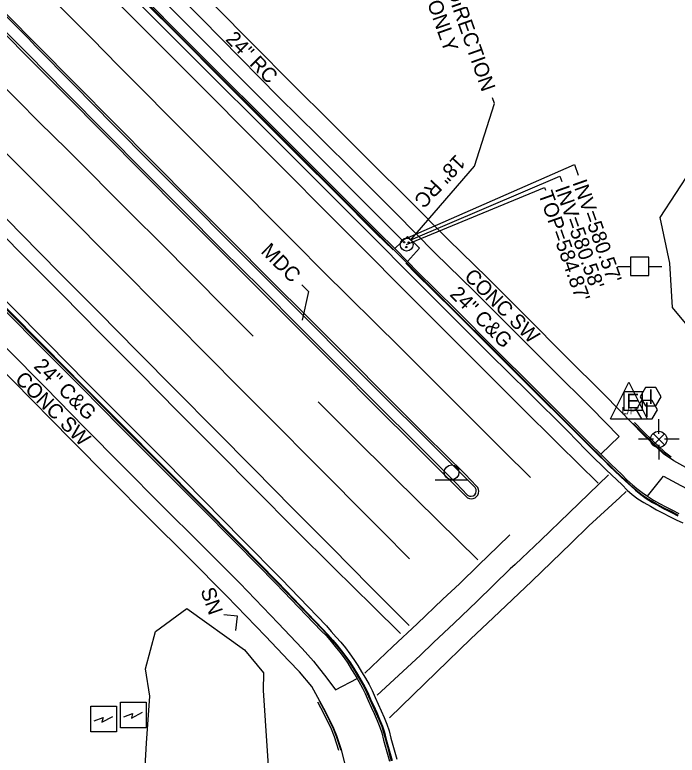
# Model space of a CAD drawing. Extents: x 2004847 to 2009016, y 1134161 to 1140101.
# Drawn here: x 2008295.3 to 2008475.6, y 1139772.3 to 1139973.7 of the extents above; entities that cross this region are included whole.
import ezdxf

# ---------------------------------------------------------------- set-up
doc = ezdxf.new("R2010")
doc.units = 0
for name, color, linetype in [('RD_EX_BldgApp', 7, 'Continuous'), ('RD_EX_Conc', 7, 'Continuous'), ('RD_EX_Curb', 7, 'Continuous'), ('RD_EX_DR_Inlet', 7, 'Continuous'), ('RD_EX_DR_Inlet_txCode', 7, 'Continuous'), ('RD_EX_DR_Pipe', 7, 'Continuous'), ('RD_EX_DR_Pipe_txCode', 7, 'Continuous'), ('RD_EX_Misc', 7, 'Continuous'), ('RD_EX_Road', 7, 'Continuous'), ('RD_EX_SU_Elec', 7, 'Continuous'), ('RD_EX_SU_Pole', 7, 'Continuous'), ('RD_EX_SU_TX_Nonpot', 7, 'Continuous'), ('RD_EX_UT', 7, 'Continuous'), ('RD_EX_VEG', 7, 'Continuous'), ('RD_Sketch3', 7, 'Continuous')]:
    doc.layers.add(name, color=color, linetype=linetype)

msp = doc.modelspace()

# ---------------------------------------------------------------- linework, layer by layer
at = {"layer": 'RD_EX_BldgApp'}
msp.add_line((2008409.72, 1139847.24), (2008418.72, 1139847.24), dxfattribs=at)
msp.add_lwpolyline([(2008355.52, 1139806.21), (2008355.97, 1139810.12), (2008352.23, 1139810.46)], dxfattribs=at)
msp.add_circle((2008414.24, 1139849.27), 2, dxfattribs=at)
at = {"layer": 'RD_EX_Conc'}
for points in [[(2008455.81, 1139870.39), (2008445.15, 1139880.94), (2008434.58, 1139891.57), (2008423.99, 1139902.16), (2008413.27, 1139912.62), (2008402.72, 1139923.27), (2008392.08, 1139933.83), (2008381.47, 1139944.43), (2008370.79, 1139954.95), (2008360.26, 1139965.62), (2008349.71, 1139976.27), (2008339.15, 1139986.9), (2008328.55, 1139997.38), (2008318.08, 1140008.11), (2008307.51, 1140018.72), (2008300.23, 1140026.14)], [(2008454.8, 1139854.23), (2008459.88, 1139859.04), (2008452.21, 1139866.78), (2008441.56, 1139877.34), (2008430.98, 1139887.97), (2008420.38, 1139898.56), (2008409.66, 1139909.02), (2008399.16, 1139919.72), (2008388.54, 1139930.3), (2008377.9, 1139940.86), (2008367.21, 1139951.38), (2008356.69, 1139962.06), (2008346.14, 1139972.71), (2008335.57, 1139983.34), (2008324.96, 1139993.84), (2008314.49, 1140004.57), (2008303.91, 1140015.18), (2008296.3, 1140022.95)], [(2008219.32, 1139957.21), (2008229.54, 1139946.87), (2008240.33, 1139936.21), (2008250.86, 1139925.54), (2008261.4, 1139914.88), (2008272.13, 1139904.31), (2008282.48, 1139893.45), (2008293.16, 1139882.93), (2008303.69, 1139872.3), (2008314.18, 1139861.59), (2008324.74, 1139850.94), (2008335.32, 1139840.28), (2008346.01, 1139829.71), (2008356.58, 1139819.08), (2008367.03, 1139808.19), (2008373.6, 1139801.37)], [(2008215.56, 1139953.88), (2008225.95, 1139943.38), (2008236.76, 1139932.69), (2008247.29, 1139922.02), (2008257.84, 1139911.37), (2008268.61, 1139900.82), (2008278.97, 1139889.96), (2008289.64, 1139879.44), (2008300.17, 1139868.81), (2008310.66, 1139858.1), (2008321.21, 1139847.45), (2008331.8, 1139836.79), (2008342.5, 1139826.21), (2008353.07, 1139815.57), (2008363.54, 1139804.68), (2008369.92, 1139797.95)], [(2008527.85, 1139868.64), (2008519.87, 1139860.43), (2008516.05, 1139856.68), (2008512.22, 1139852.93), (2008509.74, 1139851.08), (2008507.16, 1139849.33), (2008505.4, 1139848.51), (2008502.42, 1139847.24), (2008499.59, 1139846.5), (2008497.28, 1139846.2), (2008495.25, 1139846.12), (2008493.73, 1139846.1), (2008490.49, 1139846.26), (2008488.14, 1139846.52), (2008485.43, 1139847.17), (2008482.57, 1139848.22), (2008478.8, 1139850.09), (2008474.68, 1139852.36), (2008471.89, 1139854.32), (2008468.58, 1139857.43), (2008465.97, 1139859.95), (2008463.56, 1139862.43), (2008455.81, 1139870.39)], [(2008467.52, 1139842.75), (2008471.87, 1139848.22), (2008476.63, 1139845.66), (2008480.47, 1139843.69), (2008484.23, 1139842.24), (2008487.35, 1139841.68), (2008490.16, 1139841.35), (2008494.2, 1139841.35), (2008494.33, 1139834.12)], [(2008373.6, 1139801.37), (2008376.68, 1139797.89), (2008380.31, 1139793.28), (2008382.62, 1139790.09), (2008388.5, 1139793.17)], [(2008386.07, 1139766.5), (2008385.16, 1139770.21), (2008384.3, 1139773.78), (2008383, 1139777.53), (2008382.13, 1139779.6), (2008380.03, 1139783.98), (2008378.39, 1139786.99), (2008376.16, 1139791), (2008372.86, 1139794.95), (2008369.92, 1139797.95)]]:
    msp.add_lwpolyline(points, dxfattribs=at)
at = {"layer": 'RD_EX_Curb'}
for points in [[(2008452.16, 1139856.81), (2008447.21, 1139861.77), (2008436.58, 1139872.35), (2008425.93, 1139882.92), (2008415.36, 1139893.54), (2008404.67, 1139904.05), (2008402.5, 1139906.32), (2008402.2, 1139906.64), (2008398.74, 1139910.17), (2008394.13, 1139914.7), (2008383.54, 1139925.32), (2008372.91, 1139935.89), (2008362.31, 1139946.49), (2008351.67, 1139957.05), (2008341.09, 1139967.67), (2008330.53, 1139978.32), (2008320.12, 1139989.06), (2008312.75, 1139996.7), (2008311.85, 1139997.58), (2008305.89, 1140003.52), (2008305.41, 1140004.01), (2008294.92, 1140014.72), (2008290.94, 1140018.69)], [(2008401.91, 1139906.34), (2008398.45, 1139909.88), (2008393.84, 1139914.42), (2008383.24, 1139925.01), (2008372.63, 1139935.61), (2008362.03, 1139946.22), (2008351.41, 1139956.8), (2008340.84, 1139967.42), (2008330.28, 1139978.07), (2008319.78, 1139988.73), (2008312.37, 1139996.32), (2008311.55, 1139997.24), (2008305.63, 1140003.25), (2008305.11, 1140003.72), (2008294.6, 1140014.4), (2008290.68, 1140018.42)], [(2008267.85, 1139998.54), (2008278.41, 1139987.96), (2008280.16, 1139986.26), (2008283.69, 1139982.81), (2008288.53, 1139977.97), (2008290.45, 1139975.85), (2008299.08, 1139967.33), (2008301, 1139965.19), (2008311.48, 1139954.64), (2008322.11, 1139943.85), (2008332.65, 1139933.19), (2008343.21, 1139922.57), (2008353.8, 1139911.95), (2008364.4, 1139901.36), (2008375.07, 1139890.68), (2008385.65, 1139880.05), (2008396.18, 1139869.51), (2008406.84, 1139858.89), (2008417.47, 1139848.32), (2008420.62, 1139845.11)], [(2008398.34, 1139909.77), (2008393.69, 1139914.27), (2008383.12, 1139924.9), (2008372.48, 1139935.47), (2008361.88, 1139946.07), (2008351.27, 1139956.66), (2008340.69, 1139967.27), (2008330.13, 1139977.91), (2008319.6, 1139988.55), (2008312.22, 1139996.18), (2008311.55, 1139996.85)], [(2008287.82, 1139974.22), (2008288.25, 1139973.67), (2008298.89, 1139963.1), (2008309.35, 1139952.56), (2008320.03, 1139941.76), (2008330.59, 1139931.13), (2008341.15, 1139920.51), (2008351.73, 1139909.89), (2008362.36, 1139899.33), (2008373.04, 1139888.63), (2008383.65, 1139878.04), (2008394.17, 1139867.51), (2008404.84, 1139856.88), (2008415.44, 1139846.27), (2008418.59, 1139843.07)], [(2008225.08, 1139962.17), (2008234.98, 1139952.15), (2008243.99, 1139943.03), (2008250.27, 1139936.69), (2008250.53, 1139936.45), (2008261.1, 1139925.81), (2008271.68, 1139915.13), (2008282.25, 1139904.49), (2008292.82, 1139893.87), (2008303.36, 1139883.23), (2008313.92, 1139872.59), (2008324.49, 1139861.95), (2008335.05, 1139851.29), (2008345.65, 1139840.65), (2008356.2, 1139830), (2008366.76, 1139819.26)], [(2008225.24, 1139962.31), (2008235.14, 1139952.29), (2008244.13, 1139943.18), (2008250.39, 1139936.8), (2008250.68, 1139936.59), (2008261.25, 1139925.96), (2008271.83, 1139915.27), (2008282.4, 1139904.64), (2008292.97, 1139894.01), (2008303.51, 1139883.38), (2008314.06, 1139872.73), (2008324.63, 1139862.1), (2008335.2, 1139851.44), (2008345.77, 1139840.77), (2008356.34, 1139830.13), (2008366.89, 1139819.39)], [(2008224.78, 1139961.88), (2008234.67, 1139951.84), (2008243.65, 1139942.71), (2008249.96, 1139936.38), (2008250.21, 1139936.13), (2008260.84, 1139925.56), (2008271.34, 1139914.8), (2008281.92, 1139904.17), (2008292.47, 1139893.51), (2008303, 1139882.88), (2008313.55, 1139872.22), (2008324.11, 1139861.58), (2008334.72, 1139850.97), (2008345.34, 1139840.34), (2008355.9, 1139829.69), (2008366.46, 1139818.96)], [(2008451.74, 1139856.36), (2008446.77, 1139861.33), (2008436.14, 1139871.92), (2008425.52, 1139882.5), (2008414.93, 1139893.11), (2008404.24, 1139903.61), (2008402.03, 1139905.87), (2008401.75, 1139906.17)], [(2008451.88, 1139856.49), (2008446.9, 1139861.46), (2008436.27, 1139872.04), (2008425.66, 1139882.64), (2008415.06, 1139893.24), (2008404.42, 1139903.79), (2008402.21, 1139906.04), (2008401.91, 1139906.34)], [(2008463.68, 1139862.53), (2008466.12, 1139860.1), (2008468.72, 1139857.56), (2008471.99, 1139854.49), (2008473.79, 1139853.13)], [(2008464.01, 1139862.81), (2008466.41, 1139860.39), (2008469.01, 1139857.81), (2008472.18, 1139854.84), (2008474.02, 1139853.47)], [(2008451.74, 1139856.36), (2008454.37, 1139853.77), (2008455.8, 1139852.37), (2008457.2, 1139850.94), (2008458.66, 1139849.57), (2008460.11, 1139848.2), (2008461.59, 1139846.85), (2008463.06, 1139845.5), (2008464.25, 1139844.4), (2008465.7, 1139843.19), (2008467.17, 1139842.1), (2008468.88, 1139841.08), (2008470.53, 1139840.2), (2008472.28, 1139839.23), (2008474.04, 1139838.32), (2008475.82, 1139837.41)], [(2008451.88, 1139856.49), (2008454.5, 1139853.89), (2008455.88, 1139852.5), (2008457.29, 1139851.12), (2008458.7, 1139849.73), (2008460.23, 1139848.32), (2008461.7, 1139846.96), (2008463.14, 1139845.58), (2008464.33, 1139844.51), (2008465.8, 1139843.35), (2008467.26, 1139842.28), (2008468.99, 1139841.29), (2008470.6, 1139840.36), (2008472.39, 1139839.46), (2008474.14, 1139838.56), (2008475.93, 1139837.65)], [(2008452.16, 1139856.81), (2008454.8, 1139854.23), (2008456.24, 1139852.84), (2008457.67, 1139851.43), (2008459.09, 1139850.02), (2008460.54, 1139848.65), (2008461.96, 1139847.24), (2008463.44, 1139845.89), (2008464.6, 1139844.89), (2008466.07, 1139843.76), (2008467.52, 1139842.75), (2008469.2, 1139841.7), (2008470.81, 1139840.81), (2008472.57, 1139839.85), (2008474.31, 1139838.94), (2008476.1, 1139838.03)], [(2008366.76, 1139819.26), (2008379.08, 1139806.46), (2008380.42, 1139804.98), (2008381.76, 1139803.5), (2008382.87, 1139802.17), (2008384.15, 1139800.63), (2008385.35, 1139799.03), (2008386.35, 1139797.58), (2008387.45, 1139795.91), (2008388.45, 1139794.28), (2008389.45, 1139792.55), (2008390.4, 1139790.79), (2008391.19, 1139789.27), (2008391.98, 1139787.43), (2008392.82, 1139785.62), (2008393.62, 1139783.82), (2008394.41, 1139781.98), (2008395.23, 1139780.15), (2008395.73, 1139778.49), (2008396.26, 1139776.56), (2008396.74, 1139774.61), (2008397.28, 1139772.72), (2008397.82, 1139770.79)], [(2008366.89, 1139819.39), (2008379.22, 1139806.59), (2008380.57, 1139805.11), (2008381.89, 1139803.61), (2008383.03, 1139802.29), (2008384.28, 1139800.72), (2008385.47, 1139799.12), (2008386.52, 1139797.69), (2008387.59, 1139796), (2008388.62, 1139794.38), (2008389.63, 1139792.65), (2008390.61, 1139790.91), (2008391.41, 1139789.36), (2008392.18, 1139787.52), (2008393.04, 1139785.71), (2008393.85, 1139783.91), (2008394.64, 1139782.07), (2008395.38, 1139780.21), (2008395.92, 1139778.54), (2008396.42, 1139776.6), (2008396.93, 1139774.67), (2008397.47, 1139772.77), (2008398.04, 1139770.85)], [(2008366.46, 1139818.96), (2008378.75, 1139806.16), (2008380.15, 1139804.73), (2008381.48, 1139803.24), (2008382.5, 1139801.89), (2008383.78, 1139800.35), (2008384.97, 1139798.75), (2008385.95, 1139797.34), (2008386.97, 1139795.62), (2008387.99, 1139794.03), (2008388.5, 1139793.17), (2008389.01, 1139792.31), (2008389.99, 1139790.56), (2008390.73, 1139789.07), (2008391.48, 1139787.22), (2008392.34, 1139785.41), (2008393.13, 1139783.62), (2008393.93, 1139781.78), (2008394.69, 1139779.93), (2008395.2, 1139778.34), (2008395.72, 1139776.41), (2008396.25, 1139774.48), (2008396.79, 1139772.58), (2008397.37, 1139770.67)], [(2008378.27, 1139786.93), (2008379.87, 1139783.9), (2008381.96, 1139779.54), (2008382.85, 1139777.48), (2008384.09, 1139773.71)], [(2008383.54, 1139773.55), (2008382.36, 1139777.31), (2008381.52, 1139779.39), (2008379.45, 1139783.68), (2008377.82, 1139786.7)]]:
    msp.add_lwpolyline(points, dxfattribs=at)
msp.add_ellipse((2008419.51, 1139844.19), major_axis=(-1.44, -0.17), ratio=0.999976, start_param=0.761026, end_param=3.708422, dxfattribs=at)
at = {"layer": 'RD_EX_DR_Inlet'}
msp.add_lwpolyline([(2008402.2, 1139906.64), (2008405.51, 1139910.29), (2008402.2, 1139913.4), (2008398.74, 1139910.17)], dxfattribs=at)
for centre, radius in [((2008401.98, 1139911.23), 1.75), ((2008401.31, 1139911.86), 0.175), ((2008402.54, 1139911.79), 0.175), ((2008401.89, 1139910.56), 0.175)]:
    msp.add_circle(centre, radius, dxfattribs=at)
at = {"layer": 'RD_EX_DR_Inlet_txCode'}
for points in [[(2008400.74, 1139912.47), (2008447.7, 1139932.98), (2008448.71, 1139930.12)], [(2008403.12, 1139912.55), (2008443.68, 1139929.85), (2008444.19, 1139928.39)], [(2008401.98, 1139911.23), (2008439.52, 1139926.79), (2008439.8, 1139925.99)]]:
    msp.add_lwpolyline(points, dxfattribs=at)
at = {"layer": 'RD_EX_DR_Pipe'}
for p, q in [((2008309.01, 1140004.51), (2008400.74, 1139912.47)), ((2008403.12, 1139912.55), (2008420.42, 1139932.56))]:
    msp.add_line(p, q, dxfattribs=at)
at = {"layer": 'RD_EX_DR_Pipe_txCode'}
msp.add_lwpolyline([(2008420.42, 1139932.56), (2008425.89, 1139949.57), (2008425.34, 1139951.14)], dxfattribs=at)
at = {"layer": 'RD_EX_Misc'}
for points in [[(2008454.11, 1139846.27), (2008443.41, 1139856.79), (2008432.8, 1139867.39), (2008422.19, 1139877.99), (2008411.58, 1139888.6), (2008400.98, 1139899.21), (2008390.39, 1139909.83), (2008379.79, 1139920.45), (2008369.2, 1139931.07), (2008358.61, 1139941.69), (2008348.02, 1139952.31), (2008337.42, 1139962.93), (2008326.83, 1139973.55), (2008316.24, 1139984.18), (2008305.71, 1139994.86), (2008295.17, 1140005.53), (2008286.38, 1140014.45)], [(2008277.34, 1140006.87), (2008288.12, 1139995.7), (2008295.52, 1139988.25), (2008316.29, 1139967.3), (2008323.54, 1139959.85), (2008343.87, 1139939.49), (2008351.32, 1139932), (2008371.84, 1139911.4), (2008379.17, 1139904.03), (2008400.32, 1139883.13), (2008407.65, 1139875.78), (2008428.3, 1139855.24), (2008435.72, 1139847.81)], [(2008360.19, 1139886.32), (2008352.65, 1139893.87), (2008334.87, 1139911.76), (2008327.42, 1139919.24), (2008309.57, 1139937.06), (2008302.01, 1139944.55), (2008284.22, 1139962.51), (2008276.76, 1139969.99), (2008259.08, 1139987.84), (2008257.25, 1139989.69)], [(2008247.57, 1139981.47), (2008256.08, 1139972.89), (2008263.54, 1139965.42), (2008273.72, 1139955.28), (2008283.91, 1139945.14), (2008291.52, 1139937.58), (2008311.84, 1139917.19), (2008319.33, 1139909.68), (2008339.51, 1139889.4), (2008347.05, 1139881.77), (2008357.32, 1139871.47), (2008367.59, 1139861.16), (2008374.91, 1139853.74), (2008395.26, 1139833.32), (2008402.74, 1139825.74)], [(2008402.64, 1139807.56), (2008392.09, 1139818.22), (2008381.53, 1139828.87), (2008370.97, 1139839.53), (2008360.41, 1139850.18), (2008349.85, 1139860.83), (2008339.29, 1139871.48), (2008328.73, 1139882.14), (2008318.18, 1139892.8), (2008307.63, 1139903.47), (2008297.09, 1139914.14), (2008286.55, 1139924.81), (2008276.01, 1139935.48), (2008265.47, 1139946.16), (2008254.94, 1139956.84), (2008244.41, 1139967.52), (2008238.63, 1139973.38)], [(2008235.82, 1139970.97), (2008244.84, 1139961.67), (2008255.37, 1139950.99), (2008265.9, 1139940.31), (2008276.43, 1139929.63), (2008287, 1139918.98), (2008297.57, 1139908.34), (2008308.14, 1139897.7), (2008318.7, 1139887.04), (2008329.25, 1139876.39), (2008339.81, 1139865.73), (2008350.38, 1139855.09), (2008360.97, 1139844.46), (2008371.55, 1139833.84), (2008382.19, 1139823.26), (2008392.86, 1139812.72), (2008400.36, 1139805.39)], [(2008421.37, 1139825.42), (2008410.46, 1139836.14), (2008398.6, 1139847.85), (2008386.64, 1139859.72), (2008377.93, 1139868.44)], [(2008456.96, 1139848.57), (2008446.25, 1139838.24), (2008438.47, 1139830.83), (2008433.32, 1139825.92), (2008431.52, 1139824.21), (2008430.21, 1139822.96), (2008425.65, 1139818.56), (2008421.08, 1139814.15), (2008414.9, 1139808.25), (2008409.34, 1139802.97), (2008405.63, 1139799.44), (2008393.97, 1139788.63)], [(2008397.31, 1139782.5), (2008410.08, 1139794.9), (2008419.49, 1139803.95), (2008425.55, 1139809.63), (2008436.05, 1139819.66), (2008446.81, 1139829.97), (2008451.57, 1139834.68), (2008459.99, 1139842.45), (2008461.74, 1139844.06)], [(2008416.34, 1139818.94), (2008421.64, 1139824.12), (2008426.8, 1139829.04), (2008430.12, 1139832.21)], [(2008390.62, 1139794.6), (2008398.25, 1139801.85), (2008404.83, 1139808.07), (2008411.87, 1139814.76), (2008416.34, 1139818.94)]]:
    msp.add_lwpolyline(points, dxfattribs=at)
at = {"layer": 'RD_EX_Road'}
for points in [[(2008450.78, 1139855.34), (2008445.86, 1139860.42), (2008435.23, 1139871.01), (2008424.56, 1139881.54), (2008413.97, 1139892.15), (2008403.34, 1139902.71), (2008392.76, 1139913.34), (2008382.19, 1139923.97), (2008371.54, 1139934.53), (2008360.94, 1139945.13), (2008350.32, 1139955.7), (2008339.73, 1139966.32), (2008329.14, 1139976.93), (2008318.58, 1139987.54), (2008311.13, 1139995.1), (2008303.92, 1140002.55), (2008293.43, 1140013.25), (2008289.5, 1140017.24)], [(2008268.24, 1139998.91), (2008278.8, 1139988.33), (2008280.5, 1139986.6), (2008283.98, 1139983.09), (2008288.8, 1139978.23), (2008290.81, 1139976.2), (2008299.35, 1139967.59), (2008301.35, 1139965.55), (2008311.83, 1139954.99), (2008322.5, 1139944.23), (2008333.07, 1139933.6), (2008343.63, 1139922.98), (2008354.19, 1139912.33), (2008364.78, 1139901.75), (2008375.45, 1139891.07), (2008386.06, 1139880.47), (2008396.6, 1139869.92), (2008407.25, 1139859.31), (2008417.88, 1139848.73), (2008421.04, 1139845.52)], [(2008287.23, 1139974.11), (2008287.91, 1139973.32), (2008298.48, 1139962.7), (2008308.94, 1139952.17), (2008319.65, 1139941.39), (2008330.19, 1139930.72), (2008340.74, 1139920.11), (2008351.35, 1139909.51), (2008361.94, 1139898.92), (2008372.63, 1139888.21), (2008383.22, 1139877.6), (2008393.74, 1139867.08), (2008404.41, 1139856.45), (2008415.03, 1139845.86), (2008418.17, 1139842.66)], [(2008226.19, 1139963.24), (2008236.09, 1139953.22), (2008245, 1139944.04), (2008251.55, 1139937.45), (2008262.13, 1139926.83), (2008272.75, 1139916.19), (2008283.31, 1139905.54), (2008293.87, 1139894.91), (2008304.42, 1139884.28), (2008314.97, 1139873.63), (2008325.57, 1139863.03), (2008336.16, 1139852.39), (2008346.69, 1139841.68), (2008357.25, 1139831.03), (2008367.8, 1139820.3)], [(2008450.78, 1139855.34), (2008453.42, 1139852.76), (2008454.84, 1139851.35), (2008456.29, 1139849.98), (2008457.75, 1139848.61), (2008459.2, 1139847.23), (2008460.67, 1139845.87), (2008462.03, 1139844.4), (2008463.41, 1139843.22), (2008464.96, 1139842.03), (2008466.58, 1139841.02), (2008468.35, 1139840.07), (2008470, 1139839.07), (2008471.79, 1139838.16), (2008473.56, 1139837.25), (2008475.34, 1139836.34), (2008477.16, 1139835.5)], [(2008367.8, 1139820.3), (2008380.19, 1139807.47), (2008381.48, 1139805.94), (2008382.79, 1139804.43), (2008384.07, 1139803.06), (2008385.32, 1139801.49), (2008386.51, 1139799.89), (2008387.62, 1139798.36), (2008388.69, 1139796.67), (2008389.75, 1139795.01), (2008390.77, 1139793.29), (2008391.75, 1139791.55), (2008392.62, 1139789.87), (2008393.39, 1139788.03), (2008394.25, 1139786.22), (2008395.06, 1139784.4), (2008395.85, 1139782.56), (2008396.61, 1139780.71), (2008397.19, 1139778.89), (2008397.73, 1139776.97), (2008398.24, 1139775.03), (2008398.78, 1139773.12), (2008399.35, 1139771.2)]]:
    msp.add_lwpolyline(points, dxfattribs=at)
msp.add_ellipse((2008419.62, 1139844.08), major_axis=(2.02, -0.04), ratio=0.999817, start_param=3.937121, end_param=7.099608, dxfattribs=at)
at = {"layer": 'RD_EX_SU_Elec'}
msp.add_lwpolyline([(2008466.15, 1139871.13), (2008461.15, 1139871.13), (2008461.15, 1139866.13), (2008466.15, 1139866.13)], close=True, dxfattribs=at)
at = {"layer": 'RD_EX_SU_Pole'}
for p, q in [((2008470.67, 1139859.77), (2008470.67, 1139863.77)), ((2008472.17, 1139859.77), (2008469.17, 1139856.77)), ((2008469.17, 1139859.77), (2008472.17, 1139856.77)), ((2008469.14, 1139858.32), (2008465.14, 1139858.32)), ((2008472.18, 1139858.34), (2008476.2, 1139858.34)), ((2008470.67, 1139856.77), (2008470.67, 1139852.77))]:
    msp.add_line(p, q, dxfattribs=at)
msp.add_circle((2008470.6, 1139858.2), 2.22, dxfattribs=at)
at = {"layer": 'RD_EX_SU_TX_Nonpot'}
for points in [[(2008471.3, 1139869.83), (2008469.86, 1139872.33), (2008466.97, 1139872.33), (2008465.52, 1139869.83), (2008466.97, 1139867.33), (2008469.86, 1139867.33)], [(2008470.24, 1139866.29), (2008468.8, 1139868.79), (2008465.91, 1139868.79), (2008464.46, 1139866.29), (2008465.91, 1139863.79), (2008468.8, 1139863.79)]]:
    msp.add_lwpolyline(points, close=True, dxfattribs=at)
at = {"layer": 'RD_EX_UT'}
for p, q in [((2008467.92, 1139907.83), (2008462.92, 1139907.83)), ((2008462.92, 1139907.83), (2008462.92, 1139902.83)), ((2008467.92, 1139902.83), (2008467.92, 1139907.83)), ((2008459.48, 1139905.27), (2008462.95, 1139905.27)), ((2008467.84, 1139905.27), (2008471.48, 1139905.27)), ((2008462.92, 1139902.83), (2008467.92, 1139902.83)), ((2008457.48, 1139863.79), (2008462.48, 1139873.79)), ((2008462.48, 1139873.79), (2008467.48, 1139863.79)), ((2008457.48, 1139863.79), (2008467.48, 1139863.79))]:
    msp.add_line(p, q, dxfattribs=at)
for points in [[(2008316.03, 1139778.61), (2008316.03, 1139785.61), (2008323.03, 1139785.61), (2008323.03, 1139778.61)], [(2008324.09, 1139779.76), (2008324.09, 1139786.76), (2008331.09, 1139786.76), (2008331.09, 1139779.76)]]:
    msp.add_lwpolyline(points, close=True, dxfattribs=at)
for points in [[(2008324.98, 1139782.76), (2008327.41, 1139783.66), (2008327.06, 1139782.41), (2008330.11, 1139784)], [(2008316.93, 1139781.61), (2008319.35, 1139782.51), (2008319.01, 1139781.26), (2008322.05, 1139782.85)]]:
    msp.add_lwpolyline(points, dxfattribs=at)
at = {"layer": 'RD_EX_VEG'}
for points in [[(2008480.16, 1139943.17), (2008479.45, 1139931.64), (2008470.94, 1139918.62), (2008473.55, 1139906.16), (2008474.3, 1139894.12), (2008485.86, 1139880.16), (2008501.02, 1139876.45), (2008511.88, 1139882.28), (2008533.09, 1139900.7), (2008539.02, 1139915.14)], [(2008332.09, 1139788.37), (2008330.9, 1139795.8), (2008333.6, 1139805.97), (2008342.14, 1139812.2), (2008357.82, 1139800.97), (2008363, 1139794.75), (2008362.92, 1139789.94), (2008365.17, 1139755.73), (2008362.08, 1139745.13), (2008352.57, 1139734.46), (2008352.52, 1139720.58), (2008349.93, 1139715.56), (2008341.8, 1139698.24), (2008332.44, 1139694.95), (2008324.59, 1139702.97), (2008320.54, 1139715.57), (2008323.67, 1139735.59), (2008329.41, 1139744.01), (2008331.16, 1139775.58), (2008332.09, 1139788.37)]]:
    msp.add_lwpolyline(points, dxfattribs=at)
at = {"layer": 'RD_Sketch3'}
msp.add_lwpolyline([(2008373.44, 1139900.29), (2008375.26, 1139898.48), (2008373.54, 1139890.7)], dxfattribs=at)

# ---------------------------------------------------------------- texts
at = {"layer": 'RD_EX_DR_Inlet_txCode'}
for s, p in [("INV=580.57'", (2008447.07, 1139928.12)), ("TOP=584.87'", (2008437.79, 1139925.02)), ("INV=580.58'", (2008442.31, 1139926.43))]:
    msp.add_text(s, height=4, rotation=289.4494, dxfattribs=at).set_placement(p)
at = {"layer": 'RD_EX_DR_Pipe_txCode'}
for s, rotation, p in [('PIPE DIRECTION', 289.4494, (2008408.18, 1139993.18)), ('ONLY', 289.4494, (2008407.53, 1139976.99)), ('24" RC', 314.4168, (2008352.48, 1139966.9)), ('18" RC', 226.6976, (2008415.45, 1139935.98))]:
    msp.add_text(s, height=4, rotation=rotation, dxfattribs=at).set_placement(p)
at = {"layer": 'RD_EX_SU_Elec'}
msp.add_text('E', height=4, dxfattribs=at).set_placement((2008461.76, 1139866.63))
at = {"layer": 'RD_EX_SU_TX_Nonpot'}
for p in [(2008467.69, 1139867.83), (2008466.64, 1139864.29)]:
    msp.add_text('I', height=4, dxfattribs=at).set_placement(p)
at = {"layer": 'RD_EX_UT'}
msp.add_text('L/P', height=2, dxfattribs=at).set_placement((2008460.47, 1139865.07))
at = {"layer": 'RD_Sketch3'}
for s, rotation, p in [('MDC', 315.1747, (2008362.08, 1139909.18)), ('CONC SW', 315.1747, (2008417.41, 1139902.26)), ('24" C&G', 315.1747, (2008413.51, 1139897.49)), ('24" C&G', 315.1747, (2008300.29, 1139877.88)), ('CONC SW', 315.1747, (2008295.15, 1139874.29)), ('SN', 289.4494, (2008345.83, 1139817.13))]:
    msp.add_text(s, height=4, rotation=rotation, dxfattribs=at).set_placement(p)

doc.saveas('drawing.dxf')
